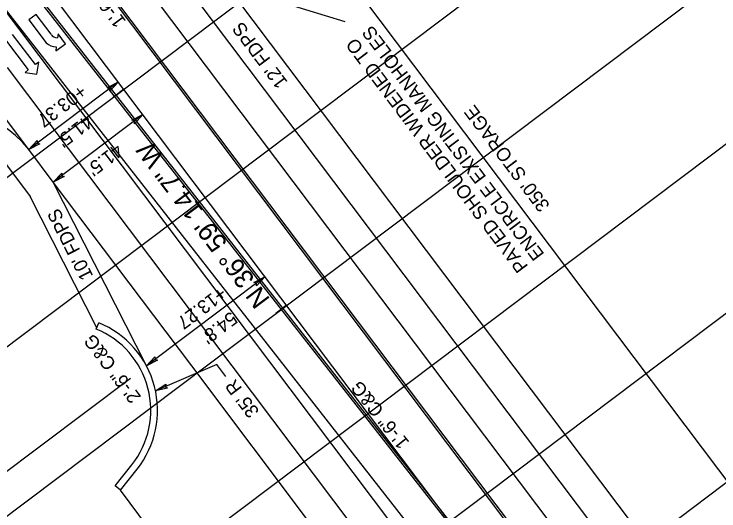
# Model space of a CAD drawing. Extents: x 1262309 to 1264352, y 775189 to 777755.
# Drawn here: x 1263122.7 to 1263383.2, y 776695.9 to 776879.5 of the extents above; entities that cross this region are included whole.
import ezdxf

# ---------------------------------------------------------------- set-up
doc = ezdxf.new("R2010")
doc.units = 0
for name, color, linetype in [('Default', 7, 'Continuous'), ('Prop Conc 1ft 6in Curb and Gutter', 7, 'Continuous'), ('Prop Conc 2ft 6in Curb and Gutter', 7, 'Continuous'), ('Prop Dimension', 7, 'Continuous'), ('Prop Dimension Text', 7, 'Continuous'), ('Prop EOT', 7, 'Continuous'), ('Prop Horizontal Alignment', 7, 'Continuous'), ('Prop Horizontal Alignment Direction Label', 7, 'Continuous'), ('Prop Horizontal Alignment Tick Small', 7, 'Continuous'), ('Prop Lane Arrow CELL', 7, 'Continuous'), ('Prop Lane Lines', 7, 'Continuous'), ('Prop Paved Shoulder', 7, 'Continuous'), ('Prop Terminator CELL', 7, 'Continuous'), ('Scratch_Level_3', 7, 'Continuous')]:
    doc.layers.add(name, color=color, linetype=linetype)

msp = doc.modelspace()

# ---------------------------------------------------------------- linework, layer by layer
at = {"layer": 'Default'}
for p, q in [((1263163.27, 776851.74), (1263163.27, 776851.74)), ((1263163.27, 776851.74), (1263163.27, 776851.74)), ((1263223.43, 776771.87), (1263223.43, 776771.87)), ((1263223.43, 776771.87), (1263223.43, 776771.87))]:
    msp.add_line(p, q, dxfattribs=at)
at = {"layer": 'Prop Conc 1ft 6in Curb and Gutter'}
for p, q in [((1263347.62, 776634.83), (1263140.59, 776909.69)), ((1263123.37, 776896.82), (1263304.93, 776664.85))]:
    msp.add_line(p, q, dxfattribs=at)
at = {"layer": 'Prop Conc 2ft 6in Curb and Gutter'}
for p, q in [((1263153.09, 776763.09), (1263154.04, 776765.41)), ((1263160.05, 776705.09), (1263166.2, 776712.86)), ((1263162.01, 776703.54), (1263160.05, 776705.09))]:
    msp.add_line(p, q, dxfattribs=at)
msp.add_arc((1263140.72, 776733.04), 32.5, 321.6137, 67.6427, dxfattribs=at)
at = {"layer": 'Prop Dimension'}
for p, q in [((1263199.74, 776954.3), (1263410.31, 776674.73)), ((1263161.24, 776854.44), (1263128.09, 776829.47)), ((1263170.33, 776842.37), (1263137.18, 776817.41)), ((1263215.41, 776782.44), (1263171.64, 776749.47)), ((1263197.58, 776749.93), (1263174.98, 776740.2)), ((1263200.89, 776745.54), (1263197.58, 776749.93)), ((1263077.93, 776678.88), (1263165.67, 776744.97))]:
    msp.add_line(p, q, dxfattribs=at)
at = {"layer": 'Prop Dimension Text'}
msp.add_lwpolyline([(1263245.11, 776876.7), (1263201.39, 776890.05)], dxfattribs=at)
msp.add_lwpolyline([(1263132.15, 776831.56), (1263128.09, 776829.47), (1263131.22, 776832.83), (1263131.25, 776831.85)], close=True, dxfattribs=at)
at = {"layer": 'Prop EOT'}
for p, q in [((1263354.56, 776666.75), (1263027.28, 777101.26)), ((1263369.15, 776607.49), (1263141.16, 776910.18)), ((1263122.79, 776896.34), (1263304.34, 776664.39)), ((1263137.18, 776817.41), (1263128.09, 776829.47)), ((1263171.64, 776749.47), (1263137.18, 776817.41)), ((1263162.01, 776703.54), (1263168.16, 776711.3)), ((1263184.58, 776673.34), (1263162.01, 776703.54))]:
    msp.add_line(p, q, dxfattribs=at)
for centre, start, end in [((1263100.13, 776808.41), 36.9874, 126.9874), ((1263140.72, 776733.04), 321.6137, 67.6465)]:
    msp.add_arc(centre, 35, start, end, dxfattribs=at)
at = {"layer": 'Prop Horizontal Alignment'}
msp.add_line((1263334.24, 776624.75), (1263127.22, 776899.61), dxfattribs=at)
at = {"layer": 'Prop Horizontal Alignment Tick Small'}
for p, q in [((1263163.27, 776851.74), (1263159.28, 776848.73)), ((1263223.43, 776771.87), (1263219.44, 776768.86))]:
    msp.add_line(p, q, dxfattribs=at)
at = {"layer": 'Prop Lane Arrow CELL'}
for p, q in [((1263130.84, 776879.35), (1263128.2, 776877.36)), ((1263128.2, 776877.36), (1263134.55, 776868.93)), ((1263136.34, 776872.04), (1263130.84, 776879.35)), ((1263130.6, 776860.84), (1263122.17, 776872.03)), ((1263138.97, 776872.2), (1263138.76, 776870.73)), ((1263141.64, 776868.58), (1263138.97, 776872.2)), ((1263119.54, 776870.04), (1263127.96, 776858.86)), ((1263138.09, 776865.97), (1263141.64, 776868.58)), ((1263138.3, 776867.44), (1263138.09, 776865.97)), ((1263131.79, 776861.75), (1263130.6, 776860.84)), ((1263131.13, 776857.3), (1263131.79, 776861.75)), ((1263127.96, 776858.86), (1263126.76, 776857.96)), ((1263126.76, 776857.96), (1263131.13, 776857.3))]:
    msp.add_line(p, q, dxfattribs=at)
for centre, radius, start, end in [((1263138.95, 776873.99), 3.27, 216.9874, 266.6456), ((1263138.21, 776872.68), 5.25, 225.6635, 270.9752)]:
    msp.add_arc(centre, radius, start, end, dxfattribs=at)
at = {"layer": 'Prop Lane Lines'}
for p, q in [((1263348.11, 776655.37), (1262839.39, 777330.78)), ((1263128.09, 776829.47), (1263058.9, 776921.33)), ((1263290.52, 776653.71), (1263113.2, 776889.12)), ((1263113.42, 776888.84), (1263294.89, 776656.99)), ((1263280.15, 776647.53), (1263120.31, 776859.74)), ((1263188.37, 776749.45), (1263137.18, 776817.41)), ((1263270.54, 776640.35), (1263188.37, 776749.45))]:
    msp.add_line(p, q, dxfattribs=at)
at = {"layer": 'Prop Paved Shoulder'}
for p, q in [((1263364.15, 776673.97), (1263021.01, 777129.53)), ((1263105.37, 776843.02), (1263128.66, 776812.1)), ((1263153.28, 776763.56), (1263128.66, 776812.1))]:
    msp.add_line(p, q, dxfattribs=at)
at = {"layer": 'Prop Terminator CELL'}
for points in [[(1263157.18, 776852.35), (1263161.24, 776854.44), (1263158.11, 776851.08), (1263158.09, 776852.06)], [(1263166.26, 776840.29), (1263170.33, 776842.37), (1263167.19, 776839.01), (1263167.17, 776840)], [(1263141.24, 776819.5), (1263137.18, 776817.41), (1263140.31, 776820.77), (1263140.33, 776819.78)], [(1263211.35, 776780.35), (1263215.41, 776782.44), (1263212.28, 776779.08), (1263212.26, 776780.06)], [(1263175.7, 776751.56), (1263171.64, 776749.47), (1263174.77, 776752.83), (1263174.79, 776751.84)], [(1263179.42, 776741.27), (1263174.98, 776740.2), (1263178.82, 776742.72), (1263178.61, 776741.76)]]:
    msp.add_lwpolyline(points, close=True, dxfattribs=at)
at = {"layer": 'Scratch_Level_3'}
for p, q in [((1262965.33, 776702.65), (1263460.43, 777075.57)), ((1262995.41, 776662.72), (1263490.52, 777035.63)), ((1263025.5, 776622.78), (1263520.6, 776995.69)), ((1263055.58, 776582.84), (1263550.68, 776955.75)), ((1263085.66, 776542.9), (1263580.76, 776915.82)), ((1263115.74, 776502.96), (1263610.84, 776875.88))]:
    msp.add_line(p, q, dxfattribs=at)

# ---------------------------------------------------------------- texts
at = {"layer": 'Prop Dimension'}
msp.add_text("35' R", height=5, rotation=127.0213, dxfattribs=at).set_placement((1263213.54, 776732.69))
at = {"layer": 'Prop Dimension Text'}
for s, rotation, p in [('1\'-6" C&G', 126.9874, (1263164.27, 776876.88)), ("12' FDPS", 126.9874, (1263224.03, 776854.38)), ('ENCIRCLE EXISTING MANHOLES', 126.9874, (1263318.85, 776790.79)), ('PAVED SHOULDER WIDENED TO ', 126.9874, (1263312.86, 776786.28)), ('+03.37', 216.9874, (1263147.17, 776853.71)), ("350' STORAGE", 126.9874, (1263320.93, 776808.82)), ("41.5'", 217.2584, (1263149.41, 776842.45)), ("41.5'", 217.2584, (1263160.5, 776831.89)), ("10' FDPS", 116.8944, (1263152.05, 776782.73)), ('+13.27', 216.9874, (1263198.9, 776779.06)), ("54.8'", 217.2584, (1263202.77, 776769.84)), ('2\'-6" C&G', 126.9874, (1263169.85, 776738.06)), ('1\'-6" C&G', 128.4214, (1263269.02, 776721.23))]:
    msp.add_text(s, height=5, rotation=rotation, dxfattribs=at).set_placement(p)
at = {"layer": 'Prop Horizontal Alignment Direction Label'}
msp.add_text('N 36%%d 59\' 14.7" W', height=7, rotation=126.9874, dxfattribs=at).set_placement((1263217.53, 776774.13))

doc.saveas('drawing.dxf')
